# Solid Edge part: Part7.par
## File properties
Author: Vicky Raina
Template: Normal.par
Last saved by: CADCIM
Revision: 9
Application: Solid Edge
Accuracy: 0.99
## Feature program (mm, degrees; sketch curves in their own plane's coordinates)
sketch for "unnamed Protrusion 1" plane through (0, 0, 0) normal (0, 0, 1) x-axis (1, 0, 0)
  line (-37.8084, 8.3373) -> (-32.6389, -42.9666)
  arc centre (-23.6843, -42.0643) radius 9 from (-32.6389, -42.9666) to (-23.6843, -51.0643) ccw
  line (-23.6843, -51.0643) -> (23.6843, -51.0643)
  arc centre (23.6843, -42.0643) radius 9 from (32.6389, -42.9666) to (23.6843, -51.0643) cw
  line (37.8084, 8.3373) -> (32.6389, -42.9666)
  arc centre (27.8588, 9.3398) radius 10 from (37.8084, 8.3373) to (28.6379, 19.3094) ccw
  line (28.6379, 19.3094) -> (1.1687, 21.4561)
  arc centre (0, 6.5017) radius 15 from (-1.1687, 21.4561) to (1.1687, 21.4561) cw
  line (-28.6379, 19.3094) -> (-1.1687, 21.4561)
  arc centre (-27.8588, 9.3398) radius 10 from (-37.8084, 8.3373) to (-28.6379, 19.3094) cw
extrude "unnamed Protrusion 1" add finite 3.175 along +normal
sketch for "ExtrudedProtrusion_2" plane through (0, -15.2312, 3.175) normal (0, 0, 1) x-axis (1, 0, 0)
  circle centre (-23.6843, -26.8331) radius 6.5
extrude "ExtrudedProtrusion_2" add finite 4 along +normal
sketch for "Hole_1" plane through (-32.8919, -42.1766, 7.175) normal (0, 0, 1) x-axis (0, 1, 0)
  hole centre (0.1123, -9.2076) bore radius 3.5
hole "Hole_1" diameter 7 through  CounterBoreDepth = 3 mm
pattern "unnamed Pattern 1" of "ExtrudedProtrusion_2", "Hole_1"
pattern "unnamed Pattern 2"
sketch for "ExtrudedProtrusion_3" plane through (0, -15.2312, 3.175) normal (0, 0, 1) x-axis (1, 0, 0)
  circle centre (0.501, -0.9588) radius 10.5
extrude "ExtrudedProtrusion_3" add finite 3.175 along +normal
sketch for "Hole_2" plane through (0, -12.0628, 6.35) normal (0, 0, 1) x-axis (1, 0, 0)
  hole centre (0.501, -4.1271) bore radius 6
hole "Hole_2" diameter 12 through
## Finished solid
Body 1: solid body, 35 faces, 58 edges, 20 vertices.
  Faces by surface: cylinder 19, plane 16
  Edges by curve: circle 38, line 20
Bounding box of the edges (mm): 75.718 x 72.566 x 7.175, from (-37.8588, -51.0643, 0) to (37.8588, 21.5017, 7.175).
Cylindrical faces by radius (mm): R3.5 x4, R4.5 x4, R6 x1, R6.5 x4, R9 x2, R10 x2, R10.5 x1, R15 x1
Planar faces by outward normal: +z 10, -y 1, -z 1, oblique 4
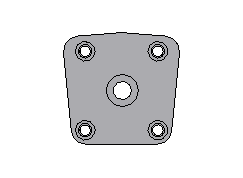
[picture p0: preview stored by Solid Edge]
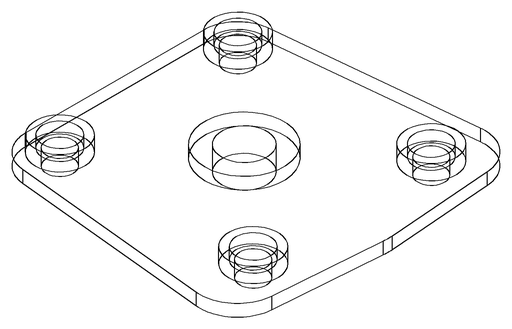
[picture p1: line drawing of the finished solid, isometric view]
